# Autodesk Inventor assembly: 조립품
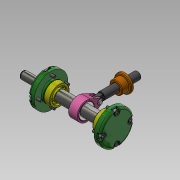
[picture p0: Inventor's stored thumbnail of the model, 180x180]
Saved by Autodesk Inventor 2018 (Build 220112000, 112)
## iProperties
Created: 2022-11
Part Number: 조립품
Material: 일반
Document SubType Name: Assembly
Designer: home
Author: home
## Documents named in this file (15)
- C:\Users\home\Desktop\721106V1003\조립품.iam
- C:\Users\home\Desktop\721106V1003\본체.ipt
- C:\Users\home\Desktop\721106V1003\앞커버.ipt
- C:\Users\home\Desktop\721106V1003\뒤커버.ipt
- C:\Users\home\Desktop\721106V1003\베어링 6201.ipt
- C:\Users\home\Desktop\721106V1003\편심축.ipt
- C:\Users\home\Desktop\721106V1003\링크.ipt
- C:\Users\home\Desktop\721106V1003\슬라이드.ipt
- C:\Users\home\Desktop\721106V1003\핀 5 x 18.ipt
- C:\Users\home\Desktop\721106V1003\고정핀 1.2 x 10.ipt
- C:\Users\home\Desktop\721106V1003\키 4 x 4 x 15.ipt
- C:\Users\home\Desktop\721106V1003\부시.ipt
- C:\Users\home\Desktop\721106V1003\V벨트풀리.ipt
- C:\Users\home\Desktop\721106V1003\멈춤나사 M3 x 8.ipt
- C:\Users\home\Desktop\721106V1003\볼트 M4 x 12.ipt
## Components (11 placed, 4 different names)
1. 핀 5 x 18:1
2. 고정핀 1.2 x 10:1
3. V벨트풀리:1
4. ISO 4762 M4 x 12:1
5. ISO 4762 M4 x 12:2
6. ISO 4762 M4 x 12:3
7. ISO 4762 M4 x 12:4
8. ISO 4762 M4 x 12:5
9. ISO 4762 M4 x 12:6
10. ISO 4762 M4 x 12:7
11. ISO 4762 M4 x 12:8
